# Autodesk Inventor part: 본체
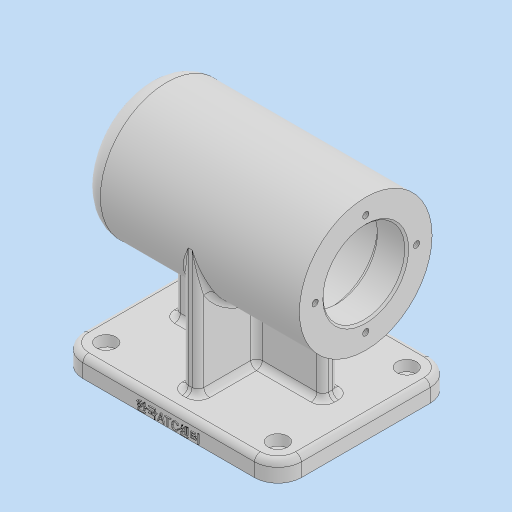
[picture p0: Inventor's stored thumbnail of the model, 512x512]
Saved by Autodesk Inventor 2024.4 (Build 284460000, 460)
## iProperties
Created: 2026-08
Part Number: 본체
Material: 일반
Document SubType Name: Modeling
Designer: home
Density: 1 g/cm^3
Appearance: 기본값
Mass: 379.96 g
Surface Area: 757.812 cm^2
Volume: 379.96 cm^3
Author: home
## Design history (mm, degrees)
sketch "스케치1"
  geometry: L1 (-56, 0)-(56, 0); L2 (-56, 0)-(-56, 34); L3 (-56, 34)-(56, 34); L4 (56, 34)-(56, 0); L5 (56, 21)-(41, 21); L6 (41, 21)-(41, 24); L7 (41, 24)-(-13, 24); L8 (-13, 24)-(-13, 21); L9 (-13, 21)-(-25, 21); L10 (-25, 21)-(-25, 17.5); L11 (-25, 17.5)-(-43, 17.5); L12 (-43, 17.5)-(-43, 16); L13 (-43, 16)-(-47, 16); L14 (-47, 16)-(-47, 10.5); L15 (-47, 10.5)-(-50, 10.5); L16 (-50, 10.5)-(-50, 0); 2 further points
  constraints: 32 end point, 12 perpendicular, 3 horizontal, 2 point on line, 1 coincident, 1 midpoint, 1 vertical
  dimensions: "d0" = 112 distance of L1.start L1.end; "d1" = 68 diameter of L3 L1; "d2" = 42 diameter of L5 L1; "d3" = 48 diameter of L7 L1; "d4" = 42 diameter of L9 L1; "d5" = 35 diameter of L11 L1; "d6" = 32 diameter of L13 L1; "d7" = 21 diameter of L15 L1; "d8" = 3 distance between parallel lines of L14 L16; "d9" = 103 distance between parallel lines of L4 L14; "d10" = 18 distance between parallel lines of L12 L10; "d11" = 81 distance between parallel lines of L4 L10; "d12" = 54 distance between parallel lines of L6 L8; "d13" = 15 distance between parallel lines of L4 L6
revolve "회전1" sketch "스케치1" stored, may be unused: angle "d14" = 90 deg
fillet "모깎기1" dims "d15" = 3
fillet "모깎기2" dims "d16" = 0.6
chamfer "모따기1" distance "d17" = 1; stored, may be unused: second distance "d18" = 2, angle "d19" = 45 deg
fillet "모깎기3" dims "d20" = 10
sketch "스케치2" dims "d21" = 52
  geometry: C1 r 34 at (0, 0) reference; 3 further points
  constraints: 2 vertical alignment, 3 other
hole "구멍1" sketch "스케치2" at (0, 26) diameter "d22" = 3.242; stored, may be unused: countersink angle "d26" = 90 deg, drill point angle "d28" = 118 deg; dims "d23" = 8, "d24" = 4, "d25" = 2, "d27" = 10
node "작업 평면1"
sketch "스케치3"
  geometry: L1 (56, -45)-(-56, -45); L2 (-56, -45)-(-56, 45); L3 (-56, 45)-(56, 45); L4 (56, 45)-(56, -45); 3 further points
  constraints: 8 end point, 2 midpoint, 2 parallel, 1 horizontal, 1 horizontal alignment, 1 perpendicular, 1 vertical alignment
  dimensions: "d33" = 112 distance of L2.end L3.end; "d34" = 90 distance of L1.end L2.end
extrude "돌출1" join sketch "스케치3" distance "d35" = 10; taper "d36" = 0 deg
sketch "스케치4"
  geometry: L1 (-4, 34)-(4, 34); L2 (4, 34)-(4, -34); L3 (4, -34)-(-4, -34); L4 (-4, -34)-(-4, 34); L5 (-38, 4)-(38, 4); L6 (38, 4)-(38, -4); L7 (38, -4)-(-38, -4); L8 (-38, -4)-(-38, 4); 9 further points
  constraints: 16 end point, 4 midpoint, 4 parallel, 2 horizontal, 2 horizontal alignment, 2 perpendicular, 2 vertical alignment
  dimensions: "d37" = 8 distance of L2.end L3.end; "d38" = 68 distance of L1.end L2.end; "d39" = 76 distance of L6.end L7.end; "d40" = 8 distance of L5.end L6.end
extrude "돌출2" join sketch "스케치4" stored distance "d41" = 10; taper "d42" = 0 deg
fillet "모깎기4" dims "d43" = 12
sketch "스케치5"
  geometry: A1 r 12 centre (44, -33) between (44, -45) and (56, -33) reference; A2 r 12 centre (-44, -33) between (-56, -33) and (-44, -45) reference; A3 r 12 centre (44, 33) between (56, 33) and (44, 45) reference; A4 r 12 centre (-44, 33) between (-44, 45) and (-56, 33) reference; 5 further points
  constraints: 4 coincident
hole "구멍2" sketch "스케치5" at (44, -33), (-44, -33), (44, 33), (-44, 33) diameter "d44" = 5.5; stored, may be unused: countersink angle "d48" = 90 deg, drill point angle "d50" = 118 deg; dims "d45" = 8, "d46" = 10, "d47" = 5.5, "d49" = 11.8
fillet "모깎기5" dims "d51" = 3
fillet "모깎기6" dims "d52" = 3
fillet "모깎기7" dims "d53" = 3
sketch "스케치6"
  geometry: L1 (0, 0)-(88, 0) reference; 2 further points
  constraints: 1 vertical alignment, 1 other
  dimensions: "d54" = 3 distance from line of L1 point (44, 3)
feature "엠보싱1" sketch "스케치6" dims "d16" = 0.6, "d55" = 0.5, "d56" = 0
feature "ʔ耀ʖ耀ʘ耀ʚ耀ʜ耀ʞ耀ʠ耀ʢ耀" dims "d0" = 112, "d1" = 68, "d2" = 42, "d3" = 48, "d4" = 42, "d5" = 35, "d6" = 32, "d7" = 21, "d8" = 3, "d9" = 103, "d10" = 18, "d11" = 81, "d12" = 54, "d13" = 15, "d14" = 90 deg, "d15" = 3, "d16" = 0.6, "d17" = 1, "d18" = 2, "d19" = 45 deg, "d20" = 10, "d21" = 52, "d22" = 3.242, "d23" = 8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
node "솔리드1"
pattern_circular "원형 패턴1" dims angle "d30" = 360 deg
feature "A9D066F2-1C7D-4E18-AEED-F7BC21143FA4" dims "d44" = 5.5, "d45" = 8, "d46" = 10, "d47" = 5.5, "d48" = 90 deg, "d49" = 11.8, "d50" = 118 deg
